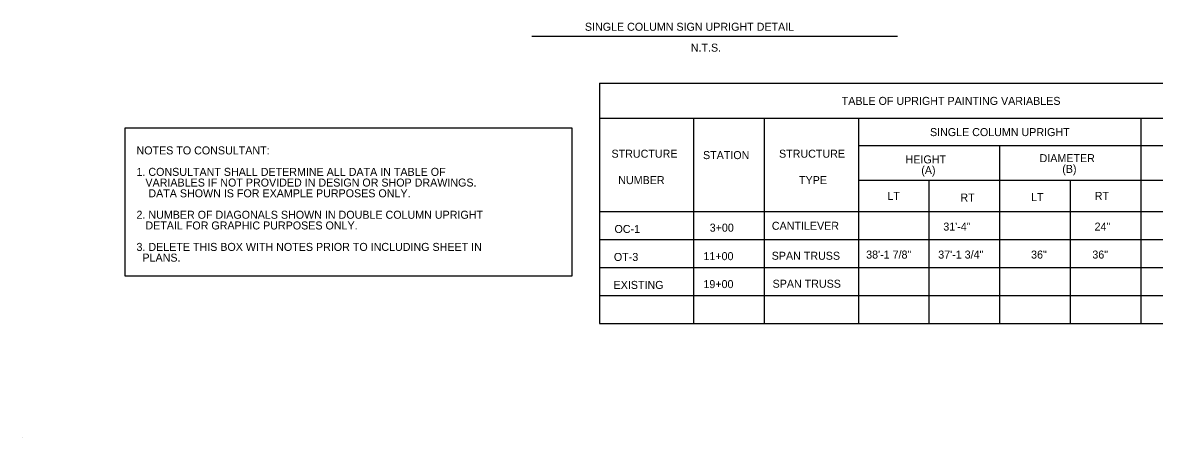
# Model space of a CAD drawing. Extents: x 10268852 to 10269008, y 2142584 to 2142686.
# Drawn here: x 10268851.6 to 10268947.8, y 2142583.9 to 2142619.1 of the extents above; entities that cross this region are included whole.
import ezdxf

# ---------------------------------------------------------------- set-up
doc = ezdxf.new("R2010")
doc.units = 0
for name, color, linetype in [('AdhocPoint_dp', 7, 'Continuous'), ('TextAlert', 7, 'Continuous'), ('TextDetails', 7, 'Continuous'), ('TextTables', 7, 'Continuous')]:
    doc.layers.add(name, color=color, linetype=linetype)

msp = doc.modelspace()

# ---------------------------------------------------------------- linework, layer by layer
at = {"layer": 'AdhocPoint_dp'}
msp.add_line((10268851.561, 2142583.858), (10268851.561, 2142583.858), dxfattribs=at)
at = {"layer": 'TextAlert'}
msp.add_lwpolyline([(10268860.237, 2142597.581), (10268898.277, 2142597.581), (10268898.277, 2142610.139), (10268860.237, 2142610.139)], close=True, dxfattribs=at)
at = {"layer": 'TextDetails'}
msp.add_line((10268894.854, 2142617.945), (10268925.92, 2142617.945), dxfattribs=at)
at = {"layer": 'TextTables'}
for p, q in [((10268900.595, 2142613.976), (10269000.595, 2142613.976)), ((10268900.595, 2142613.976), (10268900.595, 2142593.534)), ((10268900.595, 2142610.976), (10269000.595, 2142610.976)), ((10268908.595, 2142610.976), (10268908.595, 2142593.534)), ((10268914.595, 2142610.976), (10268914.595, 2142593.534)), ((10268922.595, 2142610.976), (10268922.595, 2142593.534)), ((10268946.595, 2142610.976), (10268946.595, 2142593.534)), ((10268922.595, 2142608.66), (10268994.595, 2142608.66)), ((10268934.595, 2142608.66), (10268934.595, 2142593.534)), ((10268922.595, 2142605.725), (10268994.595, 2142605.725)), ((10268928.595, 2142605.725), (10268928.595, 2142593.534)), ((10268940.595, 2142605.725), (10268940.595, 2142593.534)), ((10268900.595, 2142603.042), (10269000.595, 2142603.042)), ((10268900.595, 2142600.665), (10269000.595, 2142600.665)), ((10268900.595, 2142598.288), (10269000.595, 2142598.288)), ((10268900.595, 2142595.911), (10269000.595, 2142595.911)), ((10268900.595, 2142593.534), (10269000.595, 2142593.534))]:
    msp.add_line(p, q, dxfattribs=at)

# ---------------------------------------------------------------- texts
at = {"layer": 'TextAlert'}
for s, p in [('NOTES TO CONSULTANT:', (10268861.238, 2142607.906)), ('1. CONSULTANT SHALL DETERMINE ALL DATA IN TABLE OF', (10268861.238, 2142606.084)), ('   VARIABLES IF NOT PROVIDED IN DESIGN OR SHOP DRAWINGS.', (10268861.238, 2142605.173)), ('    DATA SHOWN IS FOR EXAMPLE PURPOSES ONLY.', (10268861.238, 2142604.261)), ('2. NUMBER OF DIAGONALS SHOWN IN DOUBLE COLUMN UPRIGHT', (10268861.238, 2142602.439)), ('   DETAIL FOR GRAPHIC PURPOSES ONLY.', (10268861.238, 2142601.528)), ('3. DELETE THIS BOX WITH NOTES PRIOR TO INCLUDING SHEET IN', (10268861.238, 2142599.705)), ('  PLANS.', (10268861.238, 2142598.794))]:
    msp.add_text(s, height=0.68, dxfattribs=at).set_placement(p)
at = {"layer": 'TextDetails'}
for s, p in [('SINGLE COLUMN SIGN UPRIGHT DETAIL', (10268899.352, 2142618.416)), ('N.T.S.', (10268908.353, 2142616.64))]:
    msp.add_text(s, height=0.68, dxfattribs=at).set_placement(p)
at = {"layer": 'TextTables'}
for s, p in [('                                     TABLE OF UPRIGHT PAINTING VARIABLES', (10268911.835, 2142612.115)), ('SINGLE COLUMN UPRIGHT', (10268928.685, 2142609.463)), ('STRUCTURE', (10268901.616, 2142607.627)), ('STATION', (10268909.392, 2142607.508)), ('STRUCTURE', (10268915.854, 2142607.627)), ('HEIGHT', (10268926.614, 2142607.142)), ('DIAMETER', (10268938, 2142607.248)), ('(A)', (10268927.944, 2142606.231)), ('(B)', (10268939.928, 2142606.337)), ('NUMBER', (10268902.189, 2142605.382)), ('TYPE', (10268917.554, 2142605.382)), ('LT', (10268925.068, 2142604.04)), ('RT', (10268931.267, 2142603.903)), ('LT', (10268937.281, 2142603.94)), ('RT', (10268942.685, 2142604.04)), ('CANTILEVER', (10268915.243, 2142601.501)), ('31\'-4"', (10268929.819, 2142601.431)), ('24"', (10268942.675, 2142601.431)), ('OC-1', (10268901.869, 2142601.229)), ('3+00', (10268909.961, 2142601.341)), ('OT-3', (10268901.817, 2142598.852)), ('11+00', (10268909.428, 2142598.92)), ('SPAN TRUSS', (10268915.23, 2142598.953)), ('38\'-1 7/8"', (10268923.261, 2142599.054)), ('37\'-1 3/4"', (10268929.387, 2142599.054)), ('36"', (10268937.279, 2142599.054)), ('36"', (10268942.485, 2142599.054)), ('19+00', (10268909.428, 2142596.543)), ('SPAN TRUSS', (10268915.306, 2142596.575)), ('EXISTING', (10268901.793, 2142596.475))]:
    msp.add_text(s, height=0.68, dxfattribs=at).set_placement(p)

doc.saveas('drawing.dxf')
